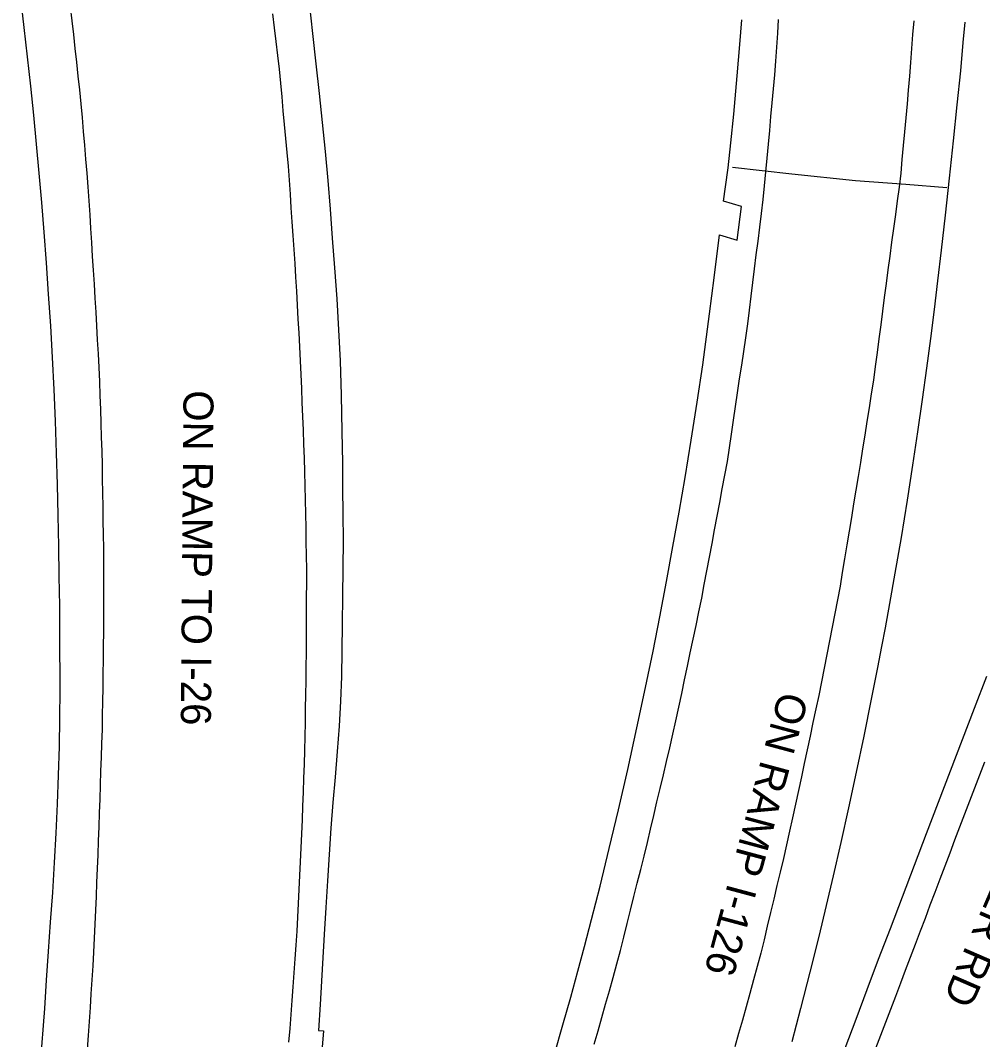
# Model space of a CAD drawing. Extents: x 1948091 to 1975253, y 787267 to 823306.
# Drawn here: x 1969052.5 to 1969225.2, y 798215 to 798398 of the extents above; entities that cross this region are included whole.
import ezdxf

# ---------------------------------------------------------------- set-up
doc = ezdxf.new("R2010")
doc.units = 0
for name, color, linetype in [('RD_EX_Conc', 7, 'Continuous'), ('RD_EX_Pavement_Markings', 7, 'Continuous'), ('RD_EX_Road', 7, 'Continuous'), ('RD_TX_RoadID', 7, 'Continuous')]:
    doc.layers.add(name, color=color, linetype=linetype)

msp = doc.modelspace()

# ---------------------------------------------------------------- linework, layer by layer
at = {"layer": 'RD_EX_Conc'}
msp.add_lwpolyline([(1969180.3, 798371.67), (1969190.98, 798370.47), (1969202.4, 798369.27), (1969211.45, 798368.65), (1969218.8, 798368.01)], dxfattribs=at)
at = {"layer": 'RD_EX_Pavement_Markings'}
for points in [[(1969061.41, 798400.47), (1969061.73, 798397.99), (1969062, 798395.51), (1969062.27, 798393.02), (1969062.54, 798390.54), (1969062.81, 798388.05), (1969063.07, 798385.56), (1969063.34, 798383.08), (1969063.56, 798380.59), (1969063.77, 798378.1), (1969063.97, 798375.61), (1969064.18, 798373.12), (1969064.39, 798370.62), (1969064.59, 798368.13), (1969064.78, 798365.64), (1969064.93, 798363.14), (1969065.09, 798360.65), (1969065.25, 798358.16), (1969065.4, 798355.66), (1969065.56, 798353.17), (1969065.71, 798350.67), (1969065.86, 798348.17), (1969066, 798345.68), (1969066.15, 798343.18), (1969066.29, 798340.69), (1969066.44, 798338.19), (1969066.58, 798335.7), (1969066.69, 798333.2), (1969066.77, 798330.7), (1969066.84, 798328.2), (1969066.92, 798325.7), (1969067, 798323.21), (1969067.08, 798320.71), (1969067.15, 798318.21), (1969067.19, 798315.71), (1969067.23, 798313.21), (1969067.26, 798310.71), (1969067.3, 798308.21), (1969067.34, 798305.71), (1969067.38, 798303.21), (1969067.39, 798300.71), (1969067.39, 798298.21), (1969067.39, 798295.71), (1969067.39, 798293.21), (1969067.39, 798290.71), (1969067.39, 798288.21), (1969067.37, 798285.71), (1969067.34, 798283.21), (1969067.3, 798280.71), (1969067.26, 798278.21), (1969067.22, 798275.71), (1969067.18, 798273.21), (1969067.14, 798270.72), (1969067.06, 798268.22), (1969066.98, 798265.72), (1969066.89, 798263.22), (1969066.81, 798260.72), (1969066.72, 798258.22), (1969066.64, 798255.73), (1969066.55, 798253.23), (1969066.47, 798250.73), (1969066.36, 798248.23), (1969066.26, 798245.73), (1969066.16, 798243.24), (1969066.06, 798240.74), (1969065.95, 798238.24), (1969065.85, 798235.74), (1969065.75, 798233.25), (1969065.64, 798230.75), (1969065.48, 798228.25), (1969065.31, 798225.76), (1969065.15, 798223.26), (1969064.99, 798220.77), (1969064.82, 798218.28), (1969064.66, 798215.78), (1969064.5, 798213.29)], [(1969097.74, 798399.21), (1969098.05, 798396.73), (1969098.36, 798394.25), (1969098.67, 798391.77), (1969098.93, 798389.29), (1969099.16, 798386.8), (1969099.4, 798384.31), (1969099.63, 798381.82), (1969099.86, 798379.33), (1969100.1, 798376.84), (1969100.33, 798374.35), (1969100.55, 798371.86), (1969100.72, 798369.37), (1969100.89, 798366.87), (1969101.06, 798364.38), (1969101.23, 798361.89), (1969101.41, 798359.39), (1969101.58, 798356.9), (1969101.75, 798354.4), (1969101.89, 798351.91), (1969102.03, 798349.41), (1969102.17, 798346.92), (1969102.31, 798344.42), (1969102.45, 798341.92), (1969102.59, 798339.43), (1969102.73, 798336.93), (1969102.85, 798334.44), (1969102.94, 798331.94), (1969103.04, 798329.44), (1969103.13, 798326.94), (1969103.23, 798324.44), (1969103.32, 798321.95), (1969103.42, 798319.45), (1969103.5, 798316.95), (1969103.55, 798314.45), (1969103.6, 798311.95), (1969103.65, 798309.45), (1969103.7, 798306.95), (1969103.75, 798304.45), (1969103.8, 798301.95), (1969103.83, 798299.45), (1969103.82, 798296.95), (1969103.81, 798294.45), (1969103.8, 798291.95), (1969103.79, 798289.45), (1969103.78, 798286.95), (1969103.77, 798284.45), (1969103.75, 798281.95), (1969103.71, 798279.45), (1969103.67, 798276.96), (1969103.63, 798274.46), (1969103.58, 798271.96), (1969103.54, 798269.46), (1969103.49, 798266.96), (1969103.41, 798264.46), (1969103.32, 798261.96), (1969103.24, 798259.46), (1969103.15, 798256.96), (1969103.07, 798254.47), (1969102.97, 798251.97), (1969102.84, 798249.47), (1969102.72, 798246.97), (1969102.59, 798244.48), (1969102.46, 798241.98), (1969102.34, 798239.48), (1969102.21, 798236.99), (1969102.09, 798234.49), (1969101.91, 798232), (1969101.74, 798229.5), (1969101.56, 798227.01), (1969101.38, 798224.52), (1969101.2, 798222.02), (1969101.02, 798219.53), (1969100.84, 798217.04), (1969100.64, 798214.54)], [(1969155.51, 798214.18), (1969156.19, 798216.59), (1969156.86, 798218.99), (1969157.54, 798221.4), (1969158.22, 798223.8), (1969158.89, 798226.2), (1969159.57, 798228.61), (1969160.21, 798231.02), (1969160.82, 798233.44), (1969161.43, 798235.86), (1969162.03, 798238.29), (1969162.64, 798240.71), (1969163.24, 798243.13), (1969163.85, 798245.56), (1969164.46, 798247.98), (1969165.06, 798250.4), (1969165.63, 798252.83), (1969166.2, 798255.26), (1969166.77, 798257.7), (1969167.34, 798260.13), (1969167.91, 798262.56), (1969168.48, 798264.99), (1969169.05, 798267.42), (1969169.62, 798269.85), (1969170.18, 798272.29), (1969170.69, 798274.73), (1969171.21, 798277.17), (1969171.72, 798279.62), (1969172.24, 798282.06), (1969172.75, 798284.5), (1969173.27, 798286.95), (1969173.78, 798289.39), (1969174.29, 798291.83), (1969174.81, 798294.28), (1969175.27, 798296.73), (1969175.73, 798299.19), (1969176.19, 798301.64), (1969176.65, 798304.1), (1969177.11, 798306.55), (1969177.57, 798309.01), (1969178.03, 798311.46), (1969178.49, 798313.92), (1969178.95, 798316.37), (1969179.41, 798318.83), (1969179.78, 798321.3), (1969180.15, 798323.77), (1969180.51, 798326.24), (1969180.88, 798328.71), (1969181.25, 798331.18), (1969181.61, 798333.65), (1969181.98, 798336.12), (1969182.34, 798338.59), (1969182.71, 798341.07), (1969183.06, 798343.54), (1969183.37, 798346.02), (1969183.68, 798348.5), (1969183.99, 798350.98), (1969184.29, 798353.46), (1969184.6, 798355.94), (1969184.91, 798358.42), (1969185.21, 798360.9), (1969185.52, 798363.38), (1969185.83, 798365.86), (1969186.08, 798368.34), (1969186.31, 798370.83), (1969186.54, 798373.32), (1969186.77, 798375.81), (1969187, 798378.3), (1969187.23, 798380.78), (1969187.46, 798383.27), (1969187.69, 798385.76), (1969187.92, 798388.25), (1969188.11, 798390.74), (1969188.27, 798393.23), (1969188.44, 798395.73), (1969188.6, 798398.22)], [(1969212.87, 798397.98), (1969212.67, 798395.49), (1969212.48, 798393), (1969212.28, 798390.5), (1969212.08, 798388.01), (1969211.88, 798385.52), (1969211.66, 798383.04), (1969211.43, 798380.55), (1969211.21, 798378.06), (1969210.98, 798375.57), (1969210.75, 798373.08), (1969210.53, 798370.59), (1969210.23, 798368.11), (1969209.89, 798365.64), (1969209.56, 798363.16), (1969209.23, 798360.69), (1969208.9, 798358.21), (1969208.57, 798355.73), (1969208.24, 798353.26), (1969207.91, 798350.78), (1969207.58, 798348.3), (1969207.26, 798345.83), (1969206.93, 798343.35), (1969206.6, 798340.87), (1969206.28, 798338.39), (1969205.95, 798335.92), (1969205.62, 798333.44), (1969205.25, 798330.97), (1969204.85, 798328.5), (1969204.46, 798326.04), (1969204.06, 798323.57), (1969203.67, 798321.1), (1969203.28, 798318.64), (1969202.88, 798316.17), (1969202.48, 798313.7), (1969202.07, 798311.24), (1969201.67, 798308.78), (1969201.26, 798306.31), (1969200.85, 798303.85), (1969200.44, 798301.38), (1969200.03, 798298.92), (1969199.63, 798296.45), (1969199.17, 798294), (1969198.7, 798291.55), (1969198.22, 798289.1), (1969197.74, 798286.64), (1969197.26, 798284.19), (1969196.79, 798281.74), (1969196.31, 798279.29), (1969195.8, 798276.84), (1969195.29, 798274.4), (1969194.77, 798271.96), (1969194.25, 798269.51), (1969193.74, 798267.07), (1969193.22, 798264.63), (1969192.69, 798262.19), (1969192.15, 798259.75), (1969191.61, 798257.31), (1969191.07, 798254.87), (1969190.53, 798252.43), (1969190, 798249.99), (1969189.46, 798247.56), (1969188.89, 798245.12), (1969188.31, 798242.69), (1969187.74, 798240.26), (1969187.16, 798237.83), (1969186.58, 798235.4), (1969186.01, 798232.97), (1969185.43, 798230.55), (1969184.76, 798228.14), (1969184.1, 798225.73), (1969183.43, 798223.33), (1969182.76, 798220.92), (1969182.1, 798218.51), (1969181.43, 798216.11), (1969180.76, 798213.7)], [(1969225.55, 798264.82), (1969224.65, 798262.49), (1969223.75, 798260.16), (1969222.86, 798257.83), (1969221.98, 798255.49), (1969221.09, 798253.15), (1969220.21, 798250.82), (1969219.32, 798248.48), (1969218.44, 798246.15), (1969217.55, 798243.81), (1969216.67, 798241.47), (1969215.78, 798239.14), (1969214.9, 798236.8), (1969214.01, 798234.47), (1969213.13, 798232.13), (1969212.24, 798229.79), (1969211.35, 798227.46), (1969210.46, 798225.13), (1969209.57, 798222.79), (1969208.69, 798220.46), (1969207.8, 798218.12), (1969206.91, 798215.79), (1969206.02, 798213.45)]]:
    msp.add_lwpolyline(points, dxfattribs=at)
at = {"layer": 'RD_EX_Road'}
for points in [[(1969052.49, 798402.01), (1969053.12, 798396.75), (1969053.72, 798391.49), (1969054.29, 798386.24), (1969054.82, 798381.01), (1969055.33, 798375.8), (1969055.8, 798370.61), (1969056.25, 798365.36), (1969056.69, 798359.99), (1969057.1, 798354.5), (1969057.5, 798348.87), (1969057.87, 798343.19), (1969058.2, 798337.49), (1969058.47, 798331.78), (1969058.7, 798326.06), (1969058.89, 798320.36), (1969059.06, 798314.72), (1969059.2, 798309.14), (1969059.31, 798303.62), (1969059.41, 798298.2), (1969059.48, 798292.91), (1969059.53, 798287.75), (1969059.56, 798277.76), (1969059.51, 798272.73), (1969059.42, 798267.65), (1969059.28, 798262.52), (1969059.09, 798257.34), (1969058.85, 798252.1), (1969058.56, 798246.81), (1969058.22, 798241.45), (1969057.86, 798236.12), (1969057.5, 798230.87), (1969057.14, 798225.71), (1969056.79, 798220.64), (1969056.02, 798210.68)], [(1969104.32, 798401.18), (1969104.95, 798395.7), (1969105.55, 798390.23), (1969106.11, 798384.9), (1969106.66, 798379.7), (1969107.18, 798374.51), (1969107.68, 798369.3), (1969108.11, 798364.13), (1969108.47, 798358.95), (1969108.86, 798353.59), (1969109.27, 798348.02), (1969109.61, 798342.48), (1969109.87, 798336.9), (1969110.06, 798330.75), (1969110.2, 798324.2), (1969110.29, 798318.6), (1969110.33, 798314.02), (1969110.37, 798309.41), (1969110.41, 798304.62), (1969110.4, 798299.67), (1969110.34, 798294.62), (1969110.28, 798289.67), (1969110.21, 798284.86), (1969110.11, 798280.25), (1969109.96, 798275.81), (1969109.71, 798271.32), (1969109.38, 798266.75), (1969109.01, 798262.18), (1969108.6, 798257.6), (1969108.23, 798252.97), (1969107.91, 798248.27), (1969107.61, 798243.52), (1969107.33, 798238.72), (1969107.05, 798233.89), (1969106.75, 798228.71), (1969106.31, 798221.3), (1969106.02, 798216.64), (1969106.91, 798216.58), (1969106.43, 798210.79)], [(1969148.39, 798212.44), (1969149.89, 798217.69), (1969151.29, 798222.65), (1969152.58, 798227.33), (1969153.78, 798231.73), (1969155.04, 798236.57), (1969156.56, 798242.59), (1969158.21, 798249.32), (1969159.87, 798256.29), (1969161.52, 798263.52), (1969163.17, 798271.01), (1969164.72, 798278.27), (1969166.07, 798284.77), (1969167.3, 798290.97), (1969168.49, 798297.29), (1969169.63, 798303.6), (1969170.73, 798309.73), (1969171.81, 798315.98), (1969172.92, 798322.66), (1969174, 798329.48), (1969174.99, 798336.2), (1969176.22, 798345.36), (1969177.03, 798351.81), (1969177.98, 798359.52), (1969181.14, 798358.59), (1969181.92, 798364.61), (1969178.72, 798365.59), (1969179.08, 798368.16), (1969179.53, 798371.56), (1969180.04, 798376.05), (1969180.54, 798381.19), (1969181.16, 798388.08), (1969181.64, 798393.72), (1969182.01, 798398.16)], [(1969222.01, 798397.75), (1969221.7, 798394.07), (1969221.23, 798388.96), (1969220.63, 798382.91), (1969219.96, 798376.41), (1969219.24, 798369.71), (1969218.51, 798363.06), (1969217.79, 798356.8), (1969217.14, 798351.29), (1969216.51, 798346.13), (1969215.85, 798340.94), (1969215.14, 798335.6), (1969214.38, 798329.98), (1969213.56, 798324.16), (1969212.67, 798318.16), (1969211.69, 798311.88), (1969210.59, 798305.17), (1969209.49, 798298.76), (1969208.53, 798293.36), (1969207.72, 798288.97), (1969207.09, 798285.62), (1969206.36, 798281.83), (1969205.23, 798276.13), (1969203.89, 798269.53), (1969202.54, 798263.03), (1969201.16, 798256.65), (1969199.75, 798250.39), (1969198.38, 798244.46), (1969197.13, 798239.09), (1969195.8, 798233.56), (1969194.21, 798227.16), (1969192.55, 798220.6), (1969190.99, 798214.62)], [(1969225.9, 798280.2), (1969223.71, 798274.5), (1969221.54, 798268.85), (1969219.39, 798263.23), (1969217.24, 798257.62), (1969215.09, 798251.98), (1969212.93, 798246.3), (1969210.76, 798240.59), (1969208.61, 798234.92), (1969206.5, 798229.38), (1969204.45, 798223.96), (1969202.45, 798218.66), (1969200.47, 798213.41)]]:
    msp.add_lwpolyline(points, dxfattribs=at)

# ---------------------------------------------------------------- texts
at = {"layer": 'RD_TX_RoadID'}
for s, rotation, p in [('ON RAMP TO I-26', 269.5341, (1969081.77, 798331.64)), ('TO BUSH RIVER RD', 246.5244, (1969245.43, 798285.35)), ('ON RAMP I-126', 254.9354, (1969188.8, 798277.76))]:
    msp.add_text(s, height=5.4, rotation=rotation, dxfattribs=at).set_placement(p)

doc.saveas('drawing.dxf')
